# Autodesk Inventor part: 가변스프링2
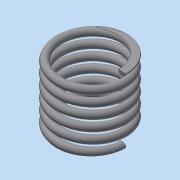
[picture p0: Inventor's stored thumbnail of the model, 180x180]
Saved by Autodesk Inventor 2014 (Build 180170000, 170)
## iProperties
Created: 2023-01
Part Number: 가변스프링2
Material: 일반
Document SubType Name: Modeling
Designer: dg
Density: 1 g/cm^3
Appearance: 기본값
Author: dg
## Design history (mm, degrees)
sketch "스케치1"
  geometry: L1 (0, 0)-(0, 17); L2 (0, 0)-(8.5, 0); L3 (0, 17)-(8.5, 17); C1 r 1 at (8.5, 0)
  constraints: 6 end point, 1 centre point, 1 coincident, 1 parallel, 1 perpendicular, 1 vertical, 1 vertical alignment
  dimensions: "d0" = 17 distance of L1.start L1.end (derived); "d1" = 8.5 distance of L1.start L2.end; "d2" = 2 diameter of C1
feature "코일1" pitch "d3" = 10; turns "d5" = 6; dims "d4" = 17 (= d0), "d6" = 0, angle "d7" = 90 deg, angle "d8" = 90 deg, "d9" = 0, "d10" = 0
node "작업 평면1"
node "작업 평면2"
feature "분할1"
feature "분할2"
node "솔리드1"
other parameters: "d11" = 0, "d12" = 0
